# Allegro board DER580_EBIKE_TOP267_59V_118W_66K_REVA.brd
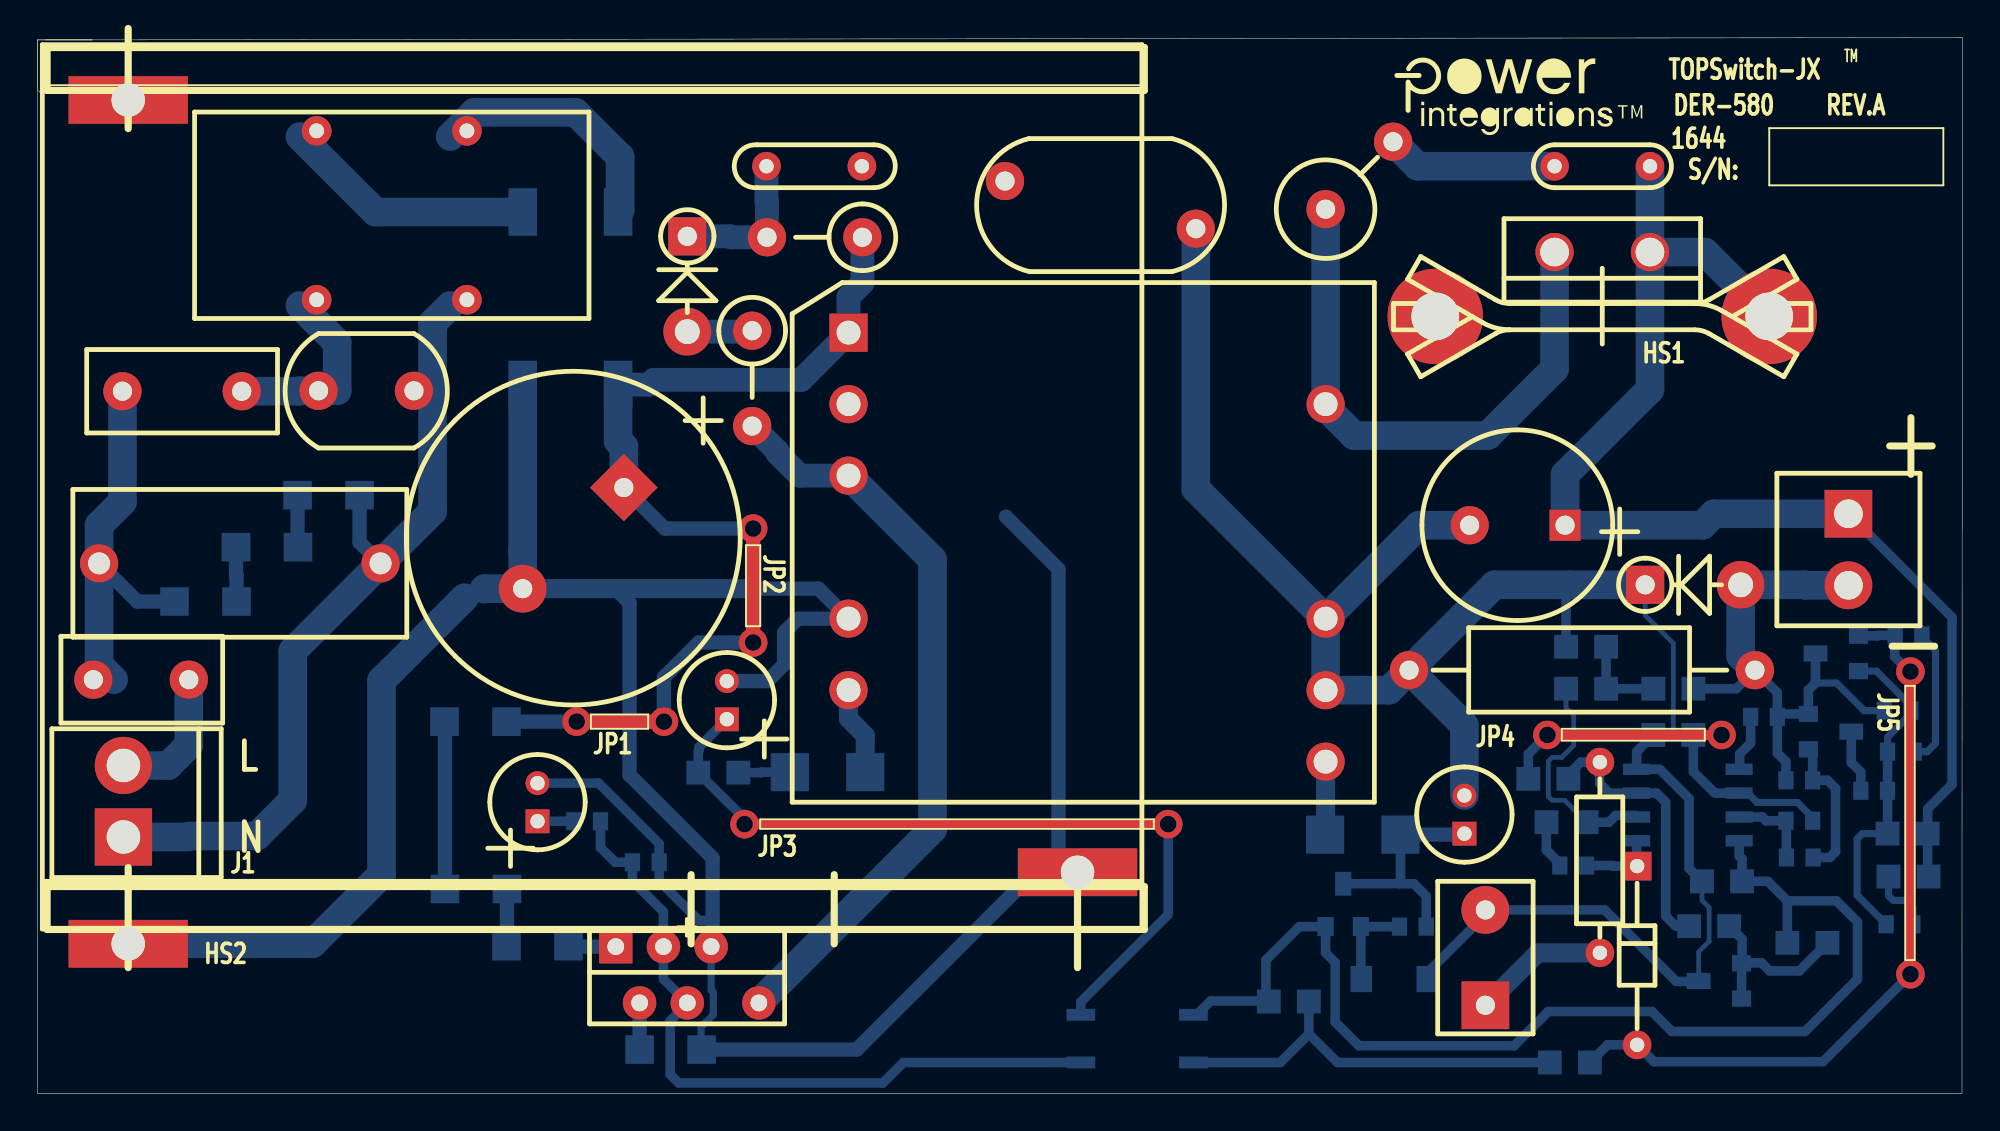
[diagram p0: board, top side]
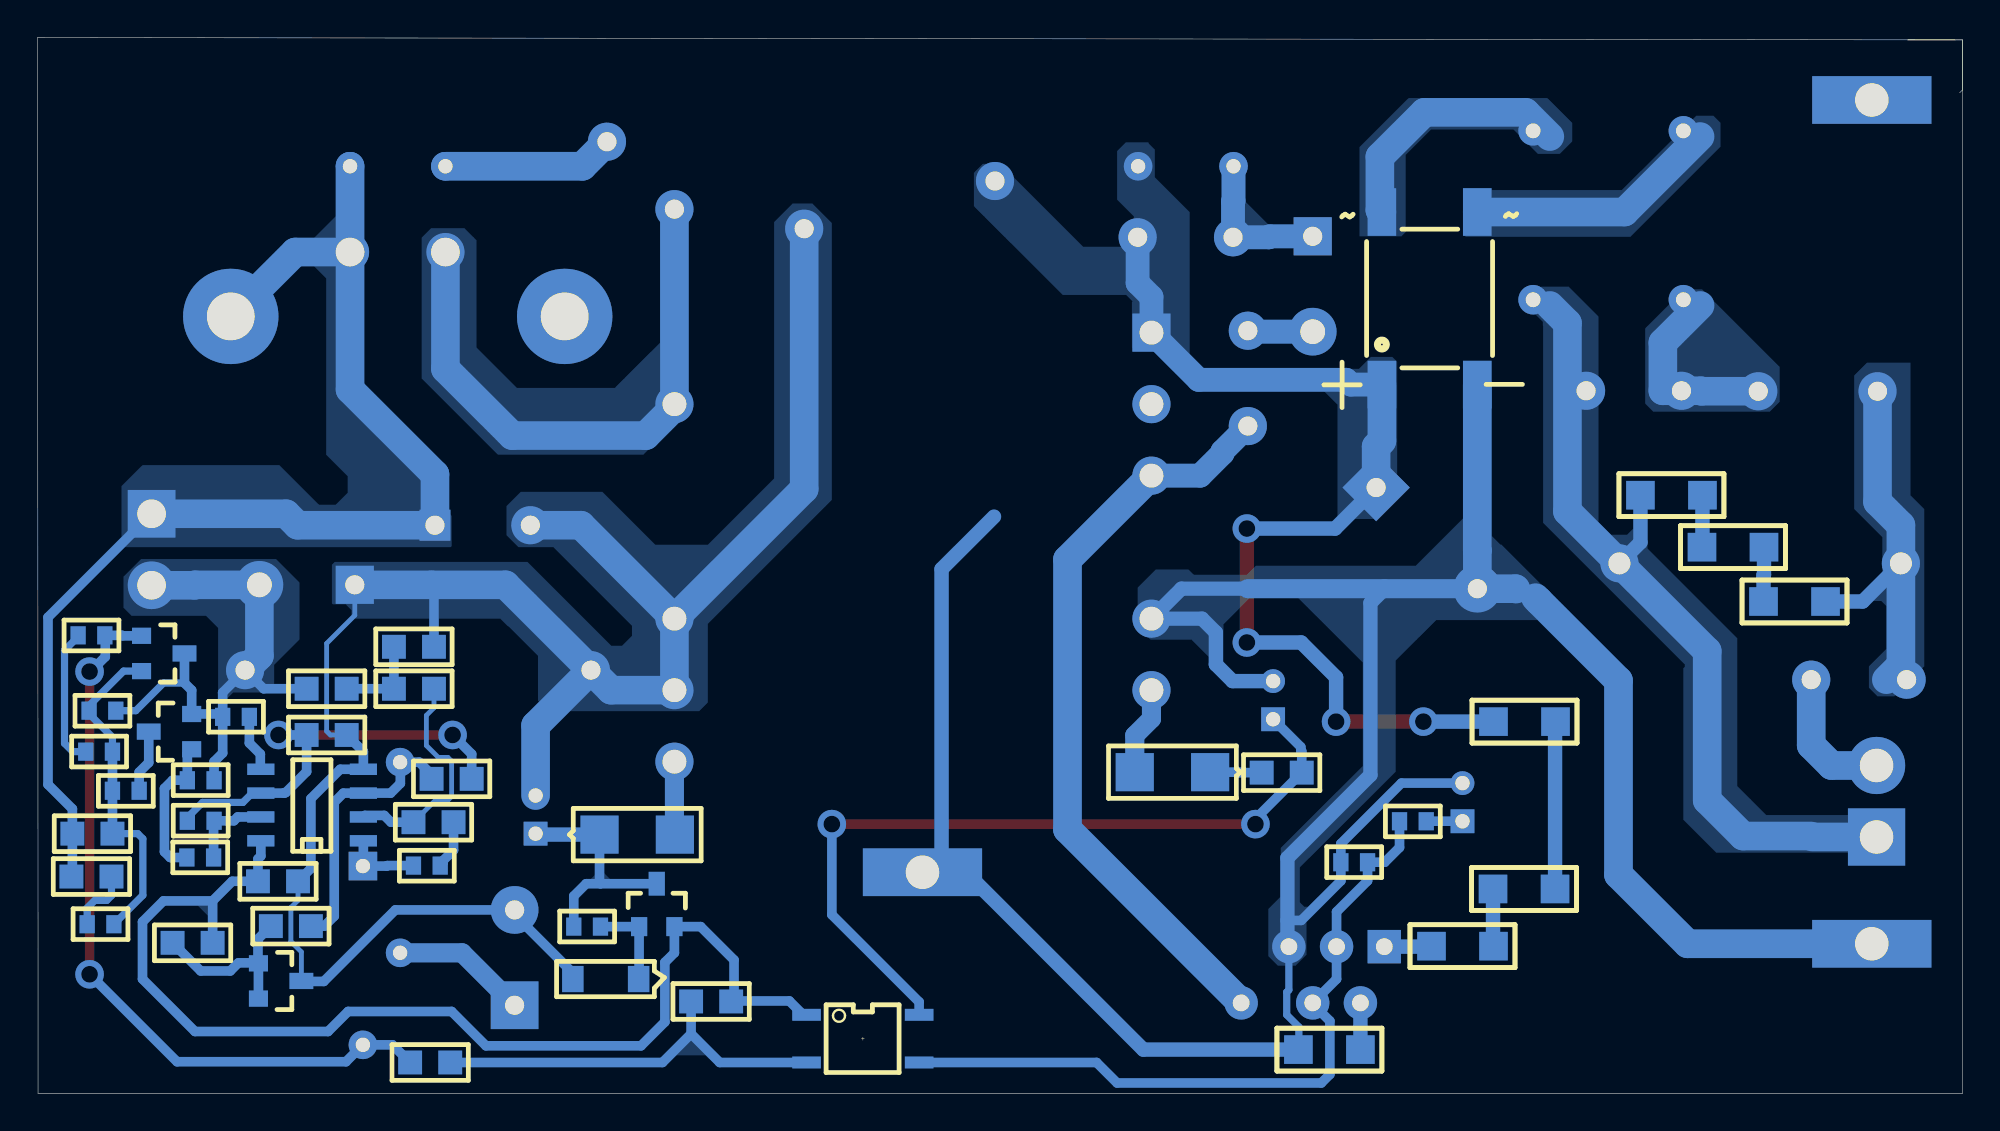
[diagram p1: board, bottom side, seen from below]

Outline 102.49 x 56.26 mm; copper layers: TOP, BOTTOM. Coordinates in mm from the lower left corner of the outline.
Outline path: 0,56.13 0,53.47 0.15,53.31 ; 0,56.13 2.92,56.13 0,56.13 ; 0,56.13 0,0 102.46,0 102.46,7.7 102.49,56.26 102.23,56.26 0.38,56.13

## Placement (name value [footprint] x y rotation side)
BR1  TBS20J-TP  [PISMD_4-TBS]  30.91 37.82 0 bottom
C1  330 nF  [PINPXCAPRAD710X315590046]  3.28 28.24 0 top
C2  82 uF  [PIPOLCAPCLYD710LS300040]  31.22 32.28 225 top
C3  2.2 nF  [PINPCAPRAD350X100200030]  38.81 49.4 0 top
C4  100 nF  [PISMC0603]  31.67 12.32 0 bottom
C5  47 uF  [PIPOLCAPCLYD200LS80030]  36.7 19.94 90 top
C6  47 uF  [PIPOLCAPCLYD200LS80030]  26.62 14.5 90 top
C7  2.2 nF  [PINPYCAPRAD540X290LS400040]  51.51 48.62 0 top
C8  220 uF  [PIPOLCAPCYLD400LS200040]  81.33 30.28 180 top
C9  220 pF  [PINPCAPRAD250X100200030]  80.77 49.4 0 top
C11  47 uF  [PIPOLCAPCLYD200LS80030]  75.97 13.84 90 top
C12  220 nF  [PISMC0603]  82.47 12.14 180 bottom
C13  330 nF  [PISMC0603]  98.5 18.21 0 bottom
C14  1 uF  [PISMC0805]  90.75 11.3 180 bottom
C15  47 nF  [PISMC0603]  93.09 14.53 0 bottom
C16  100 nF  [PISMC0805]  83.52 23.8 180 bottom
C17  4.7 nF  [PISMC0805]  98.55 11.56 0 bottom
D1  FR107-B  [PIDV200X110X040DO41]  34.59 45.67 270 top
D2  US1D  [PISMDSMA]  40.06 17.12 0 bottom
D4  1N4148  [PIDV200X080X030DO35]  85.17 12.12 270 top
D6  1N4001  [PIDV200X110X040DO41]  85.6 27.1 0 top
D7  MUR840  [PIDVT0220ACREVA]  80.77 44.83 0 top
D8  US1D  [PISMDSMA]  72.57 13.79 180 bottom
F1  3.15 A  [PI_RST_MICROFUSE]  8.05 22.05 180 top
HS1  HEATSINK  [PI_HS_TO220_VERT]  83.31 41.4 180 top
HS2  HEATSINK, MACH, PI CUST, AL 6003  [PI_HS_DER580_2]  0.51 8.74 0 top
J1  CON2  [PI_HDR_2PIN_LS156_LCK]  4.55 13.72 180 top
J2  CON2  [PI_HDR_2PIN]  96.42 30.89 180 top
L2  9 mH  [PIIND4P827X433LS315X354031]  14.86 42.29 90 top
NOREF  -  []  102.46 0 90 top
NOREF#2  -  []  -139.25 54.82 0 top
NOREF#3  -  []  0 0 0 top
NOREF#4  -  []  72.26 55.63 0 top
NOREF#5  -  []  -217.07 -144.2 0 top
Q1  MMBT4401LT1G  [PISMSOT23123_1]  94.28 20.22 90 bottom
Q2  MMBT4401LT1G  [PISMSOT23123_1]  68.58 8.89 180 bottom
R1  680 k  [PISMR1206]  7.29 26.21 0 bottom
R2  680 k  [PISMR1206]  10.57 29.11 0 bottom
R3  680 k  [PISMR1206]  13.84 31.88 0 bottom
R4  33 k  [PI1WRESD200LS725D040]  43.92 45.62 180 top
R5  33  [PI1WRESD200LS725D040]  38.05 40.64 270 top
R6  3.30 M  [PISMR1206]  24.97 19.81 180 bottom
R7  3.30 M  [PISMR1206]  21.69 10.9 0 bottom
R8  2.00 M  [PISMR1206]  24.97 7.85 0 bottom
R9  6.65 k  [PISMR1206]  32.05 2.34 0 bottom
R10  6.8  [PISMR0603]  29.97 14.5 180 bottom
R11  68  [PI1WVRESD200LS200D040]  68.58 47.12 45 top
R12  470  [PISMR0805]  80.52 1.65 0 bottom
R13  10.2 k  [PISMR0805]  79.38 16.76 0 bottom
R14  0.15  [PI2WRESD200LS725D040]  73.03 22.56 0 top
R17  3.3 k  [PISMR0603]  100.33 24.41 180 bottom
R18  3.3 k  [PISMR0805]  80.34 14.45 0 bottom
R19  10 k  [PISMR0805]  81.38 21.56 0 bottom
R20  49.9 k  [PISMR0805]  100.63 13.84 180 bottom
R21  100 k  [PISMR0805]  90.07 8.92 180 bottom
R22  2.32 k  [PISMR0603]  99.75 20.4 180 bottom
R23  6.8 k  [PISMR0805]  95.3 8.03 180 bottom
R24  1 k  [PISMR0805]  65.56 4.9 0 bottom
R25  43.2 k  [PISMR0603]  98.5 16.13 180 bottom
R26  3.32 k  [PISMR0805]  86.03 19.1 0 bottom
R27  10 k  [PISMR0603]  93.12 12.57 0 bottom
R28  4.7 k  [PISMR0603]  91.21 20.07 0 bottom
R29  10 k  [PISMR0603]  93.09 16.69 0 bottom
R30  1  [PISMR0805]  35.18 17.09 0 bottom
R31  1 k  [PISMR0805]  86.03 21.56 0 bottom
R32  2.2 k  [PISMR0603]  72.52 8.89 0 bottom
R33  13.7 k  [PI14WVRESD100LS100D030]  83.19 7.49 90 top
R34  10 k  [PISMR0603]  98.42 9.02 0 bottom
RT1  5  [PIRAD400X175LS250040]  4.52 37.41 0 top
RV1  320 Vac  [PI_DISC_335X240LS200D040]  14.96 37.44 0 top
SW1  100C  [PI_PB_SPST_TP11]  77.09 4.7 0 top
T1  PQ26/25  [PI_DER-569_XFRMR]  43.18 40.54 0 top
U1  TOP267EG  [PIICESIP76TH]  30.78 7.82 0 top
U2  PC357A  [PI_4_SMD]  58.55 2.92 270 bottom
U4  LM431BIM3/NOPB  [PISMSOT23123]  90.73 5.05 270 bottom
U5  LM358D  [PISMSO8]  85.14 13.46 90 bottom
U6  LM431BIM3/NOPB  [PISMSOT23123]  96.95 22.5 270 bottom
VR1  MMSZ5241B-7-F  [PI_SM_SOD-123_12]  70.48 6.1 0 bottom

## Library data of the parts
BR1 = DIODE BRIDGE_+-~~
C1 C3 C4 C9 C12-C17 = CAP NP
C2 = CAP POL: alternate symbols: (pi_cap_cly_d710_ls300_040_1035h)
C5 C6 C11 = CAP POL: alternate symbols: (pipolcapclyd200ls80030l460h)
C7 = CAP NP: alternate symbols: (pinpycaprad540x290ls400040h)
C8 = CAP POL
D1 D6 = DIODE: alternate symbols: (pidax475x125040do41,pidv200x110x040do41wbead,pidax390x125040do41)
D2 D7 D8 = DIODE
D4 = DIODE: alternate symbols: (pidax375x070030do35,pidv100x080x030do35)
F1 = FUSE: alternate symbols: (pirstmicrofusehoz)
HS1 = HS-PI_CUSTOM2
HS2 = HS-PI_CUSTOM_3P
J1 J2 = CON2
L2 = INDUCTOR_4P_revG
Q1 Q2 = NPN_BEC
R1-R3 R6-R10 R12-R14 R17-R32 R34 = R
R4 R5 R11 = R: alternate symbols: (pi1wvresd120ls200d040,pi1wvresd120ls300d040,pi1wvresd200ls200d040,pi1wvresd200ls300d040,pi1wvresd200ls350d040)
R33 = R: alternate symbols: (pi14wvresd100ls200d030,pi14wresd100ls400d030,pi14wresd100ls500d030)
RT1 = THERMISTOR
RV1 = VARISTOR
SW1 = SW_Thermal_NC
T1 = DER-569_XFRMR
U1 = TOP26X_EG
U2 = OPTO_A_B
U4 U6 = TL431/SOT-23_CAR
U5 = LM358
VR1 = DIODE_ZENER

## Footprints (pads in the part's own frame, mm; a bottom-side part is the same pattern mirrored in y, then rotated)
PI1WRESD200LS725D040
  round 2.032 hole 1.016: 1(0,0) 2(5.08,0)
PI1WVRESD200LS200D040
  round 2.032 hole 1.016: 1(0,0) 2(5.08,0)
PI2WRESD200LS725D040
  round 2.032 hole 1.016: 1(0,0) 2(18.415,0)
PI14WVRESD100LS100D030
  round 1.524 hole 0.762: 1(0,0) 2(10.16,0)
PI_4_SMD
  rect 0.635x1.524 smd: 1(-1.27,-2.997) 2(1.27,-2.997) 3(1.27,2.997) 4(-1.27,2.997)
PI_DER-569_XFRMR
  rect 2.032x2.032 hole 1.27: 1(0,0)
  round 2.032 hole 1.27: 2(0,-3.81) 3(0,-7.62) 4(0,-15.24) 5(0,-19.05) 7(25.4,-22.86) 8(25.4,-19.05) 9(25.4,-15.24) 11(25.4,-3.81)
PI_DISC_335X240LS200D040
  round 2.032 hole 1.016: 1(0,0) 2(5.08,0)
PI_HDR_2PIN
  rect 2.54x2.54 hole 1.524: 1(0,0)
  round 2.54 hole 1.524: 2(0,3.81)
PI_HDR_2PIN_LS156_LCK
  rect 3.048x3.048 hole 1.778: 1(-0.025,0.051)
  round 3.048 hole 1.778: 2(-0.025,-3.759)
PI_HS_DER580_2
  rect 6.35x2.54 hole 1.778: 1(4.318,-0.762) 2(54.864,3.048) 3(4.318,44.196)
PI_HS_TO220_VERT
  round 5.08 hole 2.54: 1(-8.89,0) 2(8.89,0)
PI_PB_SPST_TP11
  rect 2.54x2.54 hole 1.016: 1(0,0)
  round 2.54 hole 1.016: 2(0,5.08)
PI_RST_MICROFUSE
  round 2.032 hole 1.016: 1(0,0) 2(5.08,0)
PI_SM_SOD-123_12
  rect 1.143x1.397 smd: 1(0,0) 2(3.505,0)
PIDV200X080X030DO35
  rect 1.524x1.524 hole 0.762: 1(0,0)
  round 1.524 hole 0.762: 2(9.525,0)
PIDV200X110X040DO41
  rect 2.032x2.032 hole 1.016: 1(0,0)
  round 2.54 hole 1.321: 2(5.08,0)
PIDVT0220ACREVA
  round 2.032 hole 1.524: 1(5.08,0) 2(0,0)
PIICESIP76TH
  rect 1.778x1.778 hole 0.889: 1(0,0)
  round 1.778 hole 0.889: 2(1.27,-2.997) 3(2.54,0) 4(3.81,-2.997) 5(5.08,0) 7(7.62,-2.997)
PIIND4P827X433LS315X354031
  round 1.575 hole 0.787: 1(8.999,-8.001) 2(8.999,0) 3(0,0) 4(0,-8.001)
PINPCAPRAD250X100200030
  round 1.524 hole 0.762: 1(0,0) 2(5.08,0)
PINPCAPRAD350X100200030
  round 1.524 hole 0.762: 1(0,0) 2(5.08,0)
PINPXCAPRAD710X315590046
  round 2.032 hole 1.168: 1(0,0) 2(14.986,0)
PINPYCAPRAD540X290LS400040
  round 2.032 hole 1.016: 1(0,0) 2(10.16,-2.54)
PIPOLCAPCLYD200LS80030
  rect 1.27x1.27 hole 0.762: 1(0,0)
  round 1.27 hole 0.762: 2(2.032,0)
PIPOLCAPCLYD710LS300040
  rect 2.54x2.54 hole 1.016: 1(0,0)
  round 2.54 hole 1.016: 2(7.62,0)
PIPOLCAPCYLD400LS200040
  rect 1.651x1.651 hole 1.016: 1(0,0)
  round 2.032 hole 1.016: 2(5.08,0)
PIRAD400X175LS250040
  round 2.032 hole 1.016: 1(0,0) 2(6.35,0)
PISMC0603
  rect 0.813x0.965 smd: 1(0,0) 2(1.422,0)
PISMC0805
  rect 1.27x1.27 smd: 1(0,0) 2(2.134,0)
PISMD_4-TBS
  rect 1.524x2.54 smd: 1(0,0.051) 2(-5.08,0.051) 3(0,-9.144) 4(-5.08,-9.144)
PISMDSMA
  rect 2.032x2.032 smd: 1(0,0) 2(4.013,0)
PISMR0603
  rect 0.813x0.965 smd: 1(0,0) 2(1.422,0)
PISMR0805
  rect 1.27x1.27 smd: 1(0,0) 2(2.134,0)
PISMR1206
  rect 1.524x1.524 smd: 1(0,0) 2(3.302,0)
PISMSO8
  rect 0.61x1.448 smd: 1(0,0) 2(1.27,0) 3(2.54,0) 4(3.81,0) 5(3.81,5.461) 6(2.54,5.461) 7(1.27,5.461) 8(0,5.461)
PISMSOT23123
  rect 0.864x1.016 smd: 1(-1.88,0) 3(0,0)
  rect 0.864x1.27 smd: 2(-0.94,2.286)
PISMSOT23123_1
  rect 0.864x1.016 smd: 1(-1.88,0) 2(0,0)
  rect 0.864x1.27 smd: 3(-0.94,2.286)

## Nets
N00906: C8.1 C9.2 C17.2 D7.1 HS1.1 J2.1 R20.1
N01215: C7.2 C8.2 C11.2 C14.2 C16.2 D6.1 R14.1 R26.1 SW1.2 T1.8 T1.9 U4.2(A) U5.4(V-) VR1.2
N01329: BR1.1 C2.1 C3.2 C7.1 R4.1 R6.1 T1.1
N01364: BR1.2 C2.2 C4.2 C5.2 C6.2 HS2.1 HS2.2 R9.2 T1.4 U1.5(S)
N01421: BR1.3 L2.1
N01764: L2.3 RT1.2 RV1.1
N01812: C1.2 J1.1 L2.4 R3.2 RV1.2
N01821: R2.2 R3.1
N01839: R1.2 R2.1
N02417: C1.1 F1.2 R1.1 RT1.1
N03024: R9.1 U1.2(X)
N03093: C4.1 R10.1 U1.3(C) U1.4(F) U2.3(E)
N03111: C6.1 R10.2
N03136: R8.2 U1.1(V)
N03143: R7.2 R8.1
N03168: R6.2 R7.1
N07742: D2.1 R30.2
N07860: C5.1 R30.1 U2.4(C)
N08806: D6.2 J2.2 Q1.2(EMITTER) R14.2 R22.2 R28.2 R29.1 R31.2 U6.2(A)
N09675: R18.2 R19.1 U5.2(-IN)
N09924: C13.1 R20.2 R22.1 R25.1 R34.1 U6.3(VREF)
N16567: C3.1 D1.1 R4.2
N18059: F1.1 J1.2
N22833: R5.2 T1.3 U1.7(D)
N24164: R12.1 R24.2 U2.2(C)
N24263: C12.2 R18.1
N24295: C12.1 D4.1 U5.1(OUT)
N24455: D4.2 R12.2 R17.2 U6.1(C)
N26109: R21.1 R23.1 U4.1(C) U4.3(VREF)
N27634: R13.2 R21.2 R33.2 U5.3(+IN)
N29605: C14.1 Q2.2(EMITTER) R23.2 R24.1 U2.1(A) U5.8(V+)
N48309: D1.2 R5.1
N56239: BR1.4 L2.2
N77874: D7.2 R11.1 T1.11
N81445: C11.1 D8.1 Q2.3(COLLECTOR) R32.2
N82880: C15.2 R13.1 R26.2 U5.6(-IN)
N87772: C13.2 R17.1
N89028: C15.1 R27.1 U5.7(OUT)
N89032: Q1.1(BASE) R27.2 R29.2
N94097: C9.1 R11.2
N99851: R28.1 U5.5(+IN)
N104378: D8.2 T1.7
N110778: D2.2 T1.5
N118670: Q1.3(COLLECTOR) R25.2
N119358: C16.1 R19.2 R31.1
N133377: Q2.1(BASE) R32.1 VR1.1
N137748: R33.1 SW1.1
N145658: C17.1 R34.2

Pads without a net: HS1 2; HS2 3; T1 2

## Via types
v1: diameter 1.524, hole 0.889, TOP to BOTTOM, 10 vias

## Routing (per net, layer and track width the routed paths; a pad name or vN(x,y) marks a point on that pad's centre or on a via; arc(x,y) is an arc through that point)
N00906: length 66.3
  BOTTOM w0.508: C17.2 100.63,11.61 R20.1 100.63,15.16 101.93,16.46 101.93,25.37 J2.1
  BOTTOM w1.524: HS1.1 88.77,44.83 D7.1 ; J2.1 89.26,30.89 88.65,30.28 C8.1 81.33,32.98 85.85,37.51 D7.1 ; D7.1 C9.2
N01215: length 111.3
  BOTTOM w0.254: C14.2 88.62,10.29 89,9.91 89,8.1 88.44,7.54 U4.2 ; R26.1 86.89,19.1 87.1,19.3 87.1,23.98 85.6,25.48 D6.1
  BOTTOM w0.508: VR1.2 73.99,6.43 77.09,9.53 SW1.2 83.44,9.78 87.25,5.97 88.42,5.97 U4.2 ; 81.51,27.1 81.38,26.97 C16.2 ; C14.2 87.93,11.99 87.93,15.71 86.37,17.27 U5.4 85.14,18.21 R26.1
  BOTTOM w1.524: R14.1 75.97,19.61 C11.2 ; R14.1 71.96,21.49 T1.8 T1.9 ; R14.1 77.57,27.1 D6.1 ; T1.9 61.67,32.21 C7.2 ; T1.9 73.56,30.28 C8.2
N01329: length 54.8
  TOP w0.762: v1(38.1,30.1) v1(38.1,24.03) ; v1(33.35,19.81) v1(28.7,19.81)
  BOTTOM w0.762: v1(33.35,19.81) 33.35,22.17 35.2,24.03 v1(38.1,24.03) ; v1(38.1,30.1) 33.4,30.1 C2.1 ; R6.1 v1(28.7,19.81)
  BOTTOM w1.27: 31.11,37.97 BR1.1 32.56,37.77 32.82,38.02 40.67,38.02 T1.1 43.18,42.44 43.92,43.18 R4.1
  BOTTOM w1.524: C2.1 31.22,34.47 30.91,34.77 BR1.1
N01364: length 159.1
  BOTTOM w0.381: R9.2 35.33,2.36 35.33,3.54 35.98,4.19 35.98,5.4 35.86,5.51 U1.5
  BOTTOM w0.508: C6.2 29.87,16.54 33.1,13.31 C4.2 33.1,11.33 35.2,9.22 35.94,9.22
  BOTTOM w0.762: 51.56,30.73 54.36,27.94 54.36,12.45 55.12,11.68 ; C5.2 38.86,21.97 39.75,22.86 39.75,24.56 40.49,25.3 T1.4 41.58,26.9 38.05,26.9 ; U1.5 35.94,7.9 35.94,12.55 31.52,16.97 31.52,26.13 30.76,26.9 ; 52.96,11.68 43.61,2.34 R9.2 ; 52.96,11.68 55.12,11.68 ; 52.96,11.68 53.06,11.79 HS2.2 ; 55.5,11.94 55.24,11.68 55.12,11.68
  BOTTOM w1.016: 25.83,26.9 38.05,26.9
  BOTTOM w1.524: 22.73,26.42 18.31,22 18.31,11.66 14.63,7.98 HS2.1 ; BR1.2 25.83,28.93 25.83,28.93 25.83,26.9 23.8,26.9 23.77,26.87
N01421: length 13.5
  BOTTOM w1.524: BR1.3 31.02,47.07 31.02,49.91 28.65,52.27 23.26,52.27 21.97,50.99
N01764: length 10.5
  BOTTOM w1.524: RT1.2 13.89,37.41 13.92,37.44 RV1.1 15.95,37.44 15.95,40.01 13.97,41.99
N01812: length 43.8
  BOTTOM w0.762: R3.2 17.14,29.36 C1.2 ; 8.05,13.72 8,13.67
  BOTTOM w1.524: 8.05,13.72 11.68,13.72 13.59,15.62 13.59,23.57 C1.2 21.03,31.01 21.03,41.05 21.97,41.99 ; 8,13.67 J1.1
N01821: length 2.8
  BOTTOM w0.762: R3.1 13.84,29.13 R2.2
N01839: length 2.9
  BOTTOM w0.762: R2.1 10.57,27.64 10.59,27.61 R1.2
N02417: length 21.1
  BOTTOM w0.762: C1.1 5.31,26.21 R1.1
  BOTTOM w1.524: 4.05,22.05 3.28,22.82 C1.1 3.28,30.28 4.52,31.52 RT1.1
N03024: length 2.5
  BOTTOM w0.762: U1.2 R9.1
N03093: length 38.9
  BOTTOM w0.508: 55.63,1.65 46.1,1.65 45.01,0.56 34.14,0.56 33.68,1.02 33.68,3.86 34.59,4.78 U1.4 33.32,6.1 U1.3 33.32,9.68 31.67,11.33 C4.1 30.76,12.32 29.97,13.11 R10.1
N03111: length 1.9
  BOTTOM w0.508: C6.1 R10.2
N03136: length 2.5
  BOTTOM w0.762: U1.1 28.3,7.82 R8.2
N03143: length 3.1
  BOTTOM w0.762: R7.2 24.99,7.87 R8.1
N03168: length 8.9
  BOTTOM w0.762: R6.2 21.69,19.79 R7.1
N07742: length 2.8
  BOTTOM w0.508: R30.2 38.51,17.09 38.53,17.12 D2.1
N07860: length 42
  TOP w0.508: v1(37.64,14.35) v1(60.2,14.35)
  BOTTOM w0.508: v1(37.64,14.35) 37.64,14.63 R30.1 35.18,18.24 35.23,18.29 35.23,18.47 C5.1 36.7,20.02 ; U2.4 55.55,4.88 60.2,9.53 v1(60.2,14.35)
N08806: length 30.2
  BOTTOM w0.381: R22.2 97.26,20.4 95.78,21.87 94.67,21.87
  BOTTOM w0.508: R29.1 93.09,17.68 92.63,18.14 R28.2 ; R28.2 92.63,21.36 R14.2 90.45,21.56 R31.2 ; R28.2 92.79,20.22 Q1.2 94.28,21.49 94.67,21.87 U6.2
  BOTTOM w1.524: R14.2 90.68,23.32 D6.2 94.11,27.1 94.13,27.08 J2.2
N09675: length 12.6
  BOTTOM w0.254: 82.07,14.45 R18.2 81.31,15.62 80.64,15.62 80.44,15.82 80.44,17.7 80.64,17.91 81.15,17.91 81.79,18.54 81.79,20.14 81.38,20.55 R19.1 81.38,21.59
  BOTTOM w0.508: R18.2 83.67,14.45 84.03,14.81 85.06,14.81 U5.2
N09924: length 17.9
  BOTTOM w0.381: R20.2 97.16,13.84 96.88,13.57 96.88,10.56 R34.1 ; U6.3 97.91,22.5 99.75,20.67 R22.1 99.75,20.23 98.5,18.98 C13.1
  BOTTOM w0.508: C13.1 R25.1 R20.2 98.5,13.79
N16567: length 8.1
  BOTTOM w1.27: D1.1 36.88,45.67 36.93,45.62 R4.2 38.84,47.52 38.81,47.55 C3.1
N18059: length 7.4
  BOTTOM w1.524: F1.1 8.05,18.55 6.97,17.48 J1.2
N22833: length 40.1
  BOTTOM w1.27: T1.3 40.59,32.92 39.4,34.11 39.4,34.21 R5.2
  BOTTOM w1.524: T1.3 47.65,28.45 47.65,14.07 U1.7
N24164: length 22.1
  BOTTOM w0.508: 67.72,4.88 R24.2 67.69,3.17 ; 67.69,3.17 69.22,1.65 R12.1 ; 67.69,3.17 66.17,1.65 U2.2
  BOTTOM w0.762: 67.61,4.88 67.72,4.88
N24263: length 2.6
  BOTTOM w0.508: C12.2 80.9,12.29 80.9,12.4 80.34,12.96 R18.1
N24295: length 4.1
  BOTTOM w0.508: C12.1 83.87,12.14 83.9,12.12 D4.1 85.14,12.14 U5.1
N24455: length 40.2
  TOP w0.508: v1(99.72,22.48) v1(99.72,6.35)
  BOTTOM w0.508: v1(99.72,6.35) 95.06,1.69 86.07,1.69 D4.2 83.59,2.59 R12.2 ; v1(99.72,22.48) 99.67,22.48 98.88,23.27 98.88,24.38 R17.2 97.99,24.41 97.97,24.38 U6.1
N26109: length 9.6
  BOTTOM w0.508: 90.75,6.96 90.75,8.23 R21.1 90.04,8.94 ; 90.75,6.96 91.8,6.96 92.23,6.53 93.8,6.53 R23.1 95.33,8.05 ; 90.75,6.96 U4.1 U4.3
N27634: length 14.8
  BOTTOM w0.508: R13.2 81.51,16.99 82.17,17.65 R33.2 83.17,17.64 83.17,16.52 83.69,16 U5.3 86.21,16 86.69,15.52 86.69,9.45 87.22,8.92 R21.2
N29605: length 61
  BOTTOM w0.508: 93.17,10.26 95.78,10.26 96.9,9.14 96.9,6.1 94.11,3.3 87.02,3.3 85.95,4.37 80.44,4.37 78.61,2.54 70.36,2.54 69.09,3.81 69.09,6.99 68.58,7.49 Q2.2 67.18,8.89 65.41,7.11 65.41,5.05 65.53,4.93 ; 93.17,10.26 R23.2 93.17,8 ; 93.17,10.26 92.13,11.3 C14.1 90.75,12.5 90.6,12.65 U5.8 ; 65.53,4.93 62.46,4.93 61.72,4.19 U2.1 ; 65.53,4.93 R24.1
N48309: length 3.5
  BOTTOM w1.27: R5.1 38,40.59 D1.2
N56239: length 13.5
  BOTTOM w1.524: BR1.4 17.99,46.96 13.97,50.99
N77874: length 31.1
  BOTTOM w1.524: R11.1 T1.11 68.58,36.58 70.1,35.05 77.22,35.05 80.77,38.61 D7.2
N81445: length 12.4
  BOTTOM w0.508: R32.2 73.94,10.52 73.28,11.18 72.52,11.18 ; 72.52,11.18 72.57,11.23 D8.1 ; 72.52,11.18 Q2.3
  BOTTOM w0.762: C11.1 75.92,13.79 D8.1
N82880: length 23
  TOP w0.508: v1(89.66,19.1) v1(80.39,19.1)
  BOTTOM w0.381: C15.2 94.51,14.7 93.7,15.51 91.56,15.51 91.06,16 U5.6
  BOTTOM w0.508: U5.6 89.37,16 89.34,16.03 89.28,16.03 88.16,17.14 R26.2 v1(89.66,19.1) ; v1(80.39,19.1) 79.38,18.08 R13.1
N87772: length 7.4
  BOTTOM w0.381: 99.9,18.21 C13.2 100.61,18.21 101.05,18.66 101.05,23.61 100.33,24.33 R17.1
N89028: length 4.6
  BOTTOM w0.508: C15.1 93.12,14.5 R27.1 ; C15.1 93.12,14.53 ; C15.1 92.04,14.53 91.83,14.73 U5.7
N89032: length 7.8
  BOTTOM w0.508: R27.2 95.43,12.57 95.73,12.88 95.73,16.26 95.3,16.69 R29.2 94.51,18.11 Q1.1
N94097: length 9.1
  BOTTOM w1.524: 72.17,50.71 73.48,49.4 C9.1
N99851: length 3
  BOTTOM w0.508: R28.1 91.21,18.67 90.63,18.08 90.63,17.3 U5.5
N104378: length 3.9
  BOTTOM w1.016: T1.7 68.58,13.82 D8.2
N110778: length 4.7
  BOTTOM w1.016: T1.5 43.18,19.96 44.07,19.08 D2.2
N118670: length 3.4
  BOTTOM w0.508: Q1.3 96.57,17.63 97.08,17.12 R25.2
N119358: length 4.7
  BOTTOM w0.508: C16.1 R19.2 R31.1
N133377: length 4.9
  BOTTOM w0.508: R32.1 Q2.1 70.46,6.12 VR1.1
N137748: length 7.3
  BOTTOM w1.016: R33.1 79.88,7.49 SW1.1
N145658: length 3.4
  BOTTOM w0.381: C17.1 98.55,10.54 98.81,10.29 99.44,10.29 99.85,9.88 R34.2

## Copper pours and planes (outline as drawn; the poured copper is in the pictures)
N00906 on BOTTOM: 81.86,32.21 82.04,32.21 82.88,31.37 87.5,31.37 89.61,33.48 96.9,33.48 98.02,32.36 98.02,29.13 97.99,29.11 80.49,29.11 80.44,29.16 80.44,30.78
N00906 on BOTTOM: 85.85,47.24 86.11,47.24 88.39,44.96 88.39,44.7 87.12,43.43 87.12,34.04 85.98,32.89 85.98,32 87,30.99 81.79,30.99 81.79,33.78 85.6,37.59 85.6,47.37 85.72,47.37
N01215 on BOTTOM: 76.76,32.05 72.42,32.05 69.6,29.24 66.8,29.24 63.27,32.77 63.27,46.43 62.28,47.42 61.24,47.42 60.2,46.38 60.2,31.62 66.8,25.02 66.8,20.83 67.26,20.37 75.29,20.37 75.84,20.93 75.84,23.32 77.42,24.89 77.44,24.89 77.85,25.3 85.78,25.3 85.78,25.76 86.08,26.06 86.77,26.06 86.82,26.11 86.82,28.17 86.66,28.32 76.4,28.32 71.93,23.85 71.37,23.85 70.84,24.38 70.84,24.92 75.03,29.11 76.89,29.11 77.52,29.74 77.52,31.29
N01329 on BOTTOM: 30.1,38.99 30.1,32.38 31.24,31.24 31.24,30.73 31.37,30.61 33.27,30.61 33.27,36.7 35.18,38.61 32.13,38.61 31.5,39.24 30.35,39.24
N01329 on BOTTOM: 52.65,47.29 47.9,42.55 44.53,42.55 44.18,42.2 44.22,42.16 44.22,39.75 44.09,39.62 41.94,39.62 41.33,39.01 41.17,39.01 41.15,39.04 41.15,46.96 43,48.82 43,50.29 43.33,50.62 43.33,50.67 44.55,50.67 45.01,50.22 45.01,47.62 44.12,46.74 44.12,45.62 44.63,45.11 46.81,45.11 51.23,49.53 52.14,49.53 52.15,49.54 52.63,49.05 52.63,47.32
N01364 on BOTTOM: 26.31,30.96 26.31,30.91 29.11,28.12 37.62,28.12 38.11,27.62 38.13,27.64 40.92,27.64 41.2,27.91 42.95,27.91 43.92,26.95 43.92,24.87 43.23,24.18 41.05,24.18 39.37,22.5 39.34,22.53 39.34,24.99 37.83,26.5 35.47,26.5 31.93,22.96 31.93,17.45 36.3,13.08 36.3,10.49 36.96,9.83 36.96,7.32 36.45,6.81 35.51,6.81 34.92,7.39 34.92,9.14 34.14,9.93 34.14,9.94 35.04,9.94 35.28,10.19 35.28,12.04 30.18,17.14 30.18,23.06 28.02,25.22 22.66,25.22 21.97,25.91 21.97,26.67 24.55,29.25 24.6,29.25
N01421 on BOTTOM: 20.78,50.72 20.78,51.71 22.1,53.04 29.49,53.04 32.11,50.42 32.11,45.67 29.87,45.67 29.64,45.9 29.64,50.01 28.3,51.36 23.9,51.36 22.61,50.06 21.44,50.06
N01764 on BOTTOM: 14.81,42.85 13.87,42.85 9.73,38.71 9.73,36.86 10.26,36.32 16.46,36.32 16.89,36.75 16.89,40.77
N01812 on BOTTOM: 20.97,42.99 19.38,41.4 19.38,30.43 18.72,29.77 17.86,29.77 16.76,30.86 16.76,29.03 11.99,24.26 11.99,16.38 10.44,14.83 5.84,14.83 5.79,14.78 5.79,13.06 6.02,12.83 13.11,12.83 14.86,14.58 14.86,22.66 14.78,22.73 14.78,22.86 22.33,30.4 22.33,40.89 22.34,40.91 22.34,41.11 22.94,41.71 22.94,42.47 22.42,42.99
N02417 on BOTTOM: 2.77,38.94 2.77,31.88 2.03,31.14 2.03,22.76 3.63,21.16 4.52,21.16 4.98,21.62 4.98,22.76 4.04,23.7 4.04,25.96 4.32,26.24 4.78,26.24 5,26.47 5,26.77 4.27,27.51 4.27,29.64 5.77,31.14 5.77,38.25 5.08,38.94
N08806 on BOTTOM: 96.98,28.47 89.79,28.47 88.54,27.23 88.54,24.18 89.89,22.83 89.89,21.39 89.9,21.37 90.4,21.37 90.41,21.36 92.08,21.36 92.76,20.68 92.88,20.79 92.88,24.8 93.52,25.45 97.49,25.45 97.92,25.88 97.92,27.53
N16567 on BOTTOM: 38.73,48.08 36.3,45.64 36.35,45.59 39.01,45.59 39.01,47.8
N24164 on BOTTOM: 66.55,2.03 68.83,2.03 67.56,3.3 66.55,2.29
N56239 on BOTTOM: 12.88,50.44 17.68,45.64 26.44,45.64 26.54,45.75 26.54,47.5 25.91,48.13 18.14,48.13 14.17,52.1 13.26,52.1 12.88,51.71
N77874 on BOTTOM: 68.83,40.64 68.83,40.51 71.75,37.59 76.96,37.59 79.12,39.75 79.12,45.47 79.76,46.1 81.53,46.1 82.04,45.59 82.04,38.1 77.98,34.04 70.23,34.04 68.58,35.69 68.58,40.39

Small or netless copper shapes (teardrops, artwork), in the pictures only: 2 on BOTTOM

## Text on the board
Ref Des/Silkscreen Top: TM | JP1 | JP3 | JP4 | TOPSwitch-JX | 1644 | DER-580 | S/N: | REV.A | JP2 | JP5 | L | N | + | -
PEN17: 14.  FAB HOUSE LOGO,DATE CODE TO BE IN SILK SCREEN ONLY.DO NOT USE COPPER. | 13.  MATERIAL SINGLE SIDED FR4 COPPER 2oz THICKNESS 0.062" | Three (3) slots here:
User.5: FIGURE | SIZE | 30.0 | 31.0 | 35.0 | 40.0 | 46.0 | 50.0 | 52.0 | 60.0 | 70.0 | 100.0 | DRILL CHART: TOP to BOTTOM | ALL UNITS ARE IN MILS | PLATED | QTY | 14 | 4 | 6 | 10 | 24 | 2 | 9 | 3
